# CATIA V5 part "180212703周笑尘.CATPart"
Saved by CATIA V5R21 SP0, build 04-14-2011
Part number: 008
Bounding box of the stored display mesh (mm): x -425.314 to 132.5, y -129.34 to 53.876, z -300.487 to 20.5
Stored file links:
  C:\Users\15395\Desktop\paiqijiu.CATPart
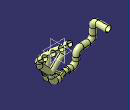
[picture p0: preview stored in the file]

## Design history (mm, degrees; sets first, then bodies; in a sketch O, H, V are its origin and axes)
Extrude1: Element1 edge of Sweep10, Lim1 90, Lim2 0, Direction Plane33
Symmetry1: ToTransfor Extrude2, Reference yz-plane
Body1 (main body)
  Sketch1 on xy-plane, origin (0, 0, 0), H (1, 0, 0), V (0, 1, 0)
    line L1 (0, 0) -> (70, 0)
    horizontal: L1 H
  Plane1: type Angle, RefPlane zx-plane, Direction Sketch1, Angle 38
  Sketch2 on Plane1, origin (0, 0, 0), H (-1, 0, 0), V (0, -0.6157, 0.788)
    point P1 (37.5, 0)
    circle A1 centre (111, 0) radius 21.5
    point P2 (111, 0)
    radius A1 = 21.5
    distance P2 V = 111
  Extrude2: Element1 Sketch2, Lim1 49, Lim2 0
  Plane2: type 1Curve, Element1 edge of Extrude2
  Plane3: type Offset, RefPlane yz-plane, Offset 112.5, reversed
  Sketch3 on Plane2, origin (0, -38.6125, -30.1674), H (1, 0, 0), V (0, -0.6157, 0.788)
    circle A1 centre (-111, 0) radius 21.5
    reference projected circle E1 centre (-111, 0) radius 21.5 from edge of Extrude2
    reference projected circle E2 centre (-111, 0) radius 21.5 from edge of Extrude2
    line L1 (-111, 0) -> (-111, -45)
    point P2 (-111, -45)
    length L1 = 45
    coincidence: A1 E1
    concentricity: A1 E2
    vertical: L1 V
  Circle1: type CtrRad, Start 128, End 180, Center Sketch3.P2, Support Plane3, Radius 45, FirstDirection (0, 1, 0)
  Sweep1: type Unspec, Profile edge of Extrude2, Guide Circle1
  Sketch4 on yz-plane, origin (0, 0, 0), H (0, 1, 0), V (0, 0, 1)
    line L1 (0, 0) -> (-90, 0)
    line L2 (-90, 0) -> (-90, -280)
    line L3 (-90, -280) -> (0, -280)
    line L4 (0, -280) -> (0, 0)
    horizontal: L1 H, L3 H
    vertical: L2 V, L4 V
  Fill1: Boundary Sketch4
  Plane4: type OffsetPt, RefPlane xy-plane, RefPoint vertex of Circle1
  Sketch5 on Plane4, origin (0, 0, -65.6279), H (1, 0, 0), V (0, 1, 0)
    point P1 (-111, -55.9078)
    line L1 (-111, -55.9078) -> (-66, -55.9078)
    point P2 (-66, -55.9078)
    reference projected point E1 (-111, -55.9078) from vertex of Circle1
    length L1 = 45
    horizontal: L1 H
    coincidence: P1 E1
  Plane5: type OffsetPt, RefPlane zx-plane, RefPoint vertex of Circle1
  Circle2: type CtrRad, Start 360, End 315, Center Sketch5.P2, Support Plane5, Radius 45, FirstDirection (-1, 0, 0)
  Sweep2: type Unspec, Profile edge of Sweep1, Guide Circle2
  Plane6: type 1Curve, Element1 edge of Sweep2
  Extrude3: Element1 edge of Sweep2, Lim1 150, Lim2 0, Direction Plane6
  Sketch6 on Plane1, origin (0, 0, 0), H (-1, 0, 0), V (0, -0.6157, 0.788)
    circle A1 centre (-37, 0) radius 21.5
    point P1 (-37, 0)
    radius A1 = 21.5
    distance P1 V = 37
    coincidence: P1 H
  Plane7: type Offset, RefPlane yz-plane, Offset 37.5
  Extrude4: Element1 Sketch6, Lim1 113, Lim2 0
  Plane8: type 1Curve, Element1 edge of Extrude4
  Sketch7 on Plane8, origin (0, -89.0452, -69.5697), H (1, 0, 0), V (0, -0.6157, 0.788)
    circle A1 centre (37, 0) radius 21.5
    reference projected circle E1 centre (37, 0) radius 21.5 from edge of Extrude4
    reference projected circle E2 centre (37, 0) radius 21.5 from edge of Extrude4
    line L1 (37, 0) -> (37, -45)
    point P2 (37, -45)
    length L1 = 45
    concentricity: A1 E1
    coincidence: A1 E2
    vertical: L1 V
  Circle3: type CtrRad, Start 128, End 180, Center Sketch7.P2, Support Plane7, Radius 45, FirstDirection (0, 1, 0)
  Sweep3: type Unspec, Profile edge of Extrude4, Guide Circle3
  Plane9: type OffsetPt, RefPlane Plane4, RefPoint vertex of Circle3
  Plane10: type OffsetPt, RefPlane Plane5, RefPoint vertex of Circle3
  Sketch8 on Plane9, origin (0, 0, -105.0302), H (1, 0, 0), V (0, 1, 0)
    point P1 (37, -106.3404)
    line L1 (37, -106.3404) -> (7, -106.3404)
    point P2 (7, -106.3404)
    reference projected point E1 (37, -106.3404) from vertex of Circle3
    length L1 = 30
    horizontal: L1 H
    coincidence: P1 E1
  Circle4: type CtrRad, Start 180, End 199, Center Sketch8.P2, Support Plane10, Radius 30, FirstDirection (-1, 0, 0)
  Sweep4: type Unspec, Profile edge of Sweep3, Guide Circle4
  Plane11: type 1Curve, Element1 edge of Sweep4
  Extrude5: Element1 edge of Sweep4, Lim1 106, Lim2 0, Direction Plane11
  Symmetry2: ToTransfor Sweep1, Reference Fill1
  Symmetry3: ToTransfor Sweep2, Reference Fill1
  Symmetry4: ToTransfor Extrude3, Reference Fill1
  Symmetry5: ToTransfor Extrude4, Reference Fill1
  Symmetry6: ToTransfor Sweep3, Reference Fill1
  Symmetry7: ToTransfor Extrude5, Reference Fill1
  Symmetry8: ToTransfor Sweep4, Reference Fill1
  Sketch9 on yz-plane, origin (0, 0, 0), H (0, 1, 0), V (0, 0, 1)
    line L1 (0, 0) -> (0, -230)
    line L2 (0, -230) -> (-55.908, -230)
    point P2 (-55.908, -230)
    line L3 (0, 0) -> (0, -230.001)
    line L4 (0, -230.001) -> (-106.34, -230.001)
    point P4 (-106.34, -230.001)
    length L2 = 55.908
    length L1 = 230
    length L3 = 230.001
    length L4 = 106.34
    vertical: L1 V, L3 V
    horizontal: L2 H, L4 H
  Plane12: type 1Curve, Element1 edge of Symmetry4
  Sketch10 on Plane12, origin (-105.88, 0, -105.88), H (0, -1, 0), V (-0.7071, 0, 0.7071)
    circle A1 centre (55.9078, -138.075) radius 21.5
    reference projected circle E1 centre (55.9078, -138.075) radius 21.5 from edge of Symmetry4
    reference projected circle E2 centre (55.9078, -138.075) radius 21.5 from edge of Symmetry4
    concentricity: A1 E1
    coincidence: A1 E2
  Plane13: type OffsetPt, RefPlane xy-plane, RefPoint Sketch9.P2
  Sketch11 on Plane13, origin (0, 0, -230), H (1, 0, 0), V (0, 1, 0)
    circle A1 centre (0, -55.908) radius 23
    point P1 (0, -55.908)
    reference projected point E1 (0, -55.908) from Sketch9.P2
    radius A1 = 23
    coincidence: P1 E1
  Extrude6: Element1 Sketch11, Lim1 30, Lim2 0
  Plane14: type 1Curve, Element1 edge of Extrude5
  Sketch12 on Plane14, origin (-69.4446, 0, -190.816), H (0, 1, 0), V (-0.9455, 0, 0.3256)
    circle A1 centre (-106.3404, -74.3507) radius 21.5
    reference projected circle E1 centre (-106.3404, -74.3507) radius 21.5 from edge of Extrude5
    reference projected circle E2 centre (-106.3404, -74.3507) radius 21.5 from edge of Extrude5
    concentricity: A1 E1
    coincidence: A1 E2
  Plane15: type OffsetPt, RefPlane Plane13, RefPoint Sketch9.P4
  Sketch13 on Plane15, origin (0, 0, -230.001), H (1, 0, 0), V (0, 1, 0)
    circle A1 centre (0, -106.34) radius 23
    point P1 (0, -106.34)
    reference projected point E1 (0, -106.34) from Sketch9.P4
    radius A1 = 23
    coincidence: P1 E1
  Extrude7: Element1 Sketch13, Lim1 15, Lim2 0
  Plane16: type OffsetPt, RefPlane zx-plane, RefPoint Sketch9.P2
  Plane17: type OffsetPt, RefPlane Plane16, RefPoint Sketch9.P4
  Sketch14 on Plane13, origin (0, 0, -230), H (1, 0, 0), V (0, 1, 0)
    point P1 (0, -106.34)
    line L1 (0, -106.34) -> (-45, -106.34)
    point P2 (-45, -106.34)
    reference projected point E1 (0, -106.34) from Sketch9.P4
    length L1 = 45
    horizontal: L1 H
    coincidence: P1 E1
  Circle5: type CtrRad, Start 180, End 270, Center Sketch14.P2, Support Plane17, Radius 45, FirstDirection (-1, 0, 0)
  Sweep5: type Unspec, Profile Sketch13, Guide Circle5
  Sketch15 on Plane13, origin (0, 0, -230), H (1, 0, 0), V (0, 1, 0)
    point P1 (0, -55.908)
    line L1 (0, -55.908) -> (-45, -55.908)
    point P2 (-45, -55.908)
    reference projected point E1 (0, -55.908) from Sketch9.P2
    length L1 = 45
    horizontal: L1 H
    coincidence: P1 E1
  Circle6: type CtrRad, Start 180, End 270, Center Sketch15.P2, Support Plane16, Radius 45, FirstDirection (-1, 0, 0)
  Sweep6: type Unspec, Profile Sketch11, Guide Circle6
  Plane18: type OffsetPt, RefPlane yz-plane, RefPoint vertex of Circle5
  Plane19: type OffsetPt, RefPlane Plane18, RefPoint vertex of Circle6
  Extrude8: Element1 edge of Sweep5, Lim1 30, Lim2 0, Direction Plane18
  Extrude9: Element1 edge of Sweep6, Lim1 30, Lim2 0, Direction Plane19
  Plane20: type Offset, RefPlane yz-plane, Offset 135, reversed
  Sketch16 on Plane20, origin (-135, 0, 0), H (0, 1, 0), V (0, 0, 1)
    line L1 (0, 0) -> (0, -275)
    line L2 (0, -275) -> (-81.124, -275)
    point P2 (-81.124, -275)
    length L1 = 275
    length L2 = 81.124
    vertical: L1 V
    horizontal: L2 H
  Plane21: type OffsetPt, RefPlane Plane19, RefPoint Sketch16.P2
  Sketch17 on Plane21, origin (-135, 0, 0), H (0, 1, 0), V (0, 0, 1)
    circle A1 centre (-81.124, -275) radius 23
    point P1 (-81.124, -275)
    reference projected point E1 (-81.124, -275) from Sketch16.P2
    radius A1 = 23
    coincidence: P1 E1
  Extrude10: Element1 Sketch17, Lim1 30, Lim2 0
  Blend1: StartLimit {blendlimit Curve edge of Extrude9, Point {extremum Reference edge of Extrude9, Direction (1, 2, 3)}, Support Extrude9}, EndLimit {blendlimit Curve Sketch17, Point {extremum Reference Sketch17, Direction (1, 2, 3)}, Support Extrude10}
  Blend2: StartLimit {blendlimit Curve edge of Extrude8, Point {extremum Reference edge of Extrude8, Direction (1, 2, 3)}, Support Extrude8}, EndLimit {blendlimit Curve Sketch17, Point {extremum Reference Sketch17, Direction (1, 2, 3)}, Support Extrude10}
  Plane22: type 1Curve, Element1 edge of Extrude10
  Sketch18 on Plane22, origin (-165, 0, 0), H (0, -1, 0), V (0, 0, 1)
    circle A1 centre (81.124, -275) radius 23
    point P1 (81.124, -275)
    reference projected circle E1 centre (81.124, -275) radius 23 from edge of Extrude10
    reference projected circle E2 centre (81.124, -275) radius 23 from edge of Extrude10
    point P2 (81.124, -275)
    coincidence: E1 A1, P2 P1
    concentricity: E2 A1
  Plane23: type OffsetPt, RefPlane yz-plane, RefPoint Sketch18.P2
  Plane24: type Offset, RefPlane Plane23, Offset 10, reversed
  Sketch19 on Plane24, origin (-175, 0, 0), H (0, 1, 0), V (0, 0, 1)
    circle A1 centre (-81.124, -275) radius 25.5
    point P1 (-81.124, -275)
    reference projected point E1 (-81.124, -275) from Sketch18.P2
    radius A1 = 25.5
    coincidence: P1 E1
  Extrude11: Element1 Sketch19, Lim1 30, Lim2 0
  Blend3: StartLimit {blendlimit Curve Sketch18.A1, Point {extremum Reference Sketch18.A1, Direction (1, 2, 3)}, Support Extrude10}, EndLimit {blendlimit Curve Sketch19, Point {extremum Reference Sketch19, Direction (1, 2, 3)}, Support Extrude11}
  Plane25: type 1Curve, Element1 edge of Extrude11
  Sketch20 on Plane25, origin (-205, 0, 0), H (0, -1, 0), V (0, 0, 1)
    circle A1 centre (81.124, -275) radius 25.5
    point P1 (81.124, -275)
    reference projected circle E1 centre (81.124, -275) radius 25.5 from edge of Extrude11
    reference projected circle E2 centre (81.124, -275) radius 25.5 from edge of Extrude11
    line L1 (81.124, -275) -> (81.124, -230)
    point P2 (81.124, -230)
    length L1 = 45
    coincidence: A1 E1
    concentricity: A1 E2
    vertical: L1 V
  Plane26: type OffsetPt, RefPlane zx-plane, RefPoint Sketch20.P1
  Circle7: type CtrRad, Start -90, End 0, Center Sketch20.P2, Support Plane26, Radius 45, FirstDirection (-1, 0, 0)
  Sweep7: type Unspec, Profile edge of Extrude11, Guide Circle7
  Plane27: type OffsetPt, RefPlane xy-plane, RefPoint vertex of Circle7
  Extrude12: Element1 edge of Sweep7, Lim1 30, Lim2 0, Direction Plane27
  Plane28: type 1Curve, Element1 edge of Extrude12
  Sketch21 on Plane28, origin (0, 0, -200), H (1, 0, 0), V (0, 1, 0)
    circle A1 centre (-250, -81.124) radius 25.5
    reference projected circle E1 centre (-250, -81.124) radius 25.5 from edge of Extrude12
    reference projected circle E2 centre (-250, -81.124) radius 25.5 from edge of Extrude12
    line L1 (-250, -81.124) -> (-295, -81.124)
    point P2 (-295, -81.124)
    length L1 = 45
    coincidence: A1 E1
    concentricity: A1 E2
    horizontal: L1 H
  Circle8: type CtrRad, Start 90, End 180, Center Sketch21.P2, Support Plane26, Radius 45, FirstDirection (-1, 0, 0)
  Sweep8: type Unspec, Profile edge of Extrude12, Guide Circle8
  Extrude13: Element1 edge of Sweep8, Lim1 60, Lim2 0, Direction Plane25
  Plane29: type 1Curve, Element1 edge of Extrude13
  Sketch22 on Plane29, origin (-355, 0, 0), H (0, 1, 0), V (0, 0, 1)
    circle A1 centre (-81.124, -155) radius 25.5
    reference projected circle E1 centre (-81.124, -155) radius 25.5 from edge of Extrude13
    reference projected circle E2 centre (-81.124, -155) radius 25.5 from edge of Extrude13
    line L1 (-81.124, -155) -> (-81.124, -110)
    point P2 (-81.124, -110)
    length L1 = 45
    coincidence: A1 E1
    concentricity: A1 E2
    vertical: L1 V
  Circle9: type CtrRad, Start 270, End 360, Center Sketch22.P2, Support Plane26, Radius 45, FirstDirection (-1, 0, 0)
  Sweep9: type Unspec, Profile edge of Extrude13, Guide Circle9
  Plane30: type OffsetPt, RefPlane xy-plane, RefPoint vertex of Circle9
  Extrude14: Element1 edge of Sweep9, Lim1 60, Lim2 0, Direction Plane30
  Plane31: type 1Curve, Element1 edge of Extrude14
  Sketch23 on Plane31, origin (0, 0, -50), H (1, 0, 0), V (0, -1, 0)
    circle A1 centre (-400, 81.124) radius 25.5
    point P1 (-400, 81.124)
    reference projected circle E1 centre (-400, 81.124) radius 25.5 from edge of Extrude14
    reference projected circle E2 centre (-400, 81.124) radius 25.5 from edge of Extrude14
    line L1 (-400, 81.124) -> (-400, 36.124)
    point P2 (-400, 36.124)
    length L1 = 45
    coincidence: A1 E1
    concentricity: A1 E2
    vertical: L1 V
  Plane32: type OffsetPt, RefPlane Plane24, RefPoint Sketch23.P1
  Circle10: type CtrRad, Start 90, End 180, Center Sketch23.P2, Support Plane32, Radius 45, FirstDirection (0, 1, 0)
  Sweep10: type Unspec, Profile edge of Extrude14, Guide Circle10
  Plane33: type OffsetPt, RefPlane Plane26, RefPoint vertex of Circle10
  Sketch24 on zx-plane, origin (0, 0, 0), H (-1, 0, 0), V (0, 0, 1)
    line L1 (-199.2031, -53.0295) -> (200.2614, -53.0295)
    line L2 (200.2614, -53.0295) -> (200.2614, -99.0636)
    line L3 (200.2614, -99.0636) -> (-199.2031, -99.0636)
    line L4 (-199.2031, -99.0636) -> (-199.2031, -53.0295)
    horizontal: L1 H, L3 H
    vertical: L2 V, L4 V
  Sketch25 on yz-plane, origin (0, 0, 0), H (0, 1, 0), V (0, 0, 1)
    line L1 (24.887, -138.1537) -> (-34.6434, -138.1537)
    line L2 (-34.6434, -138.1537) -> (-34.6434, -179.7195)
    line L3 (-34.6434, -179.7195) -> (24.887, -179.7195)
    line L4 (24.887, -179.7195) -> (24.887, -138.1537)
    point P5 (-130.3173, -138.1537)
    line L5 (-130.3173, -138.1537) -> (-185.5955, -138.1537)
    line L6 (-185.5955, -138.1537) -> (-185.5955, -179.7195)
    line L7 (-185.5955, -179.7195) -> (-130.3173, -179.7195)
    line L8 (-130.3173, -179.7195) -> (-130.3173, -138.1537)
    point P7 (-185.5955, -179.7195)
    horizontal: L1 H, L3 H, L5 H, L7 H
    vertical: L2 V, L4 V, L6 V, L8 V
    coincidence: P5 L1, P7 L3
